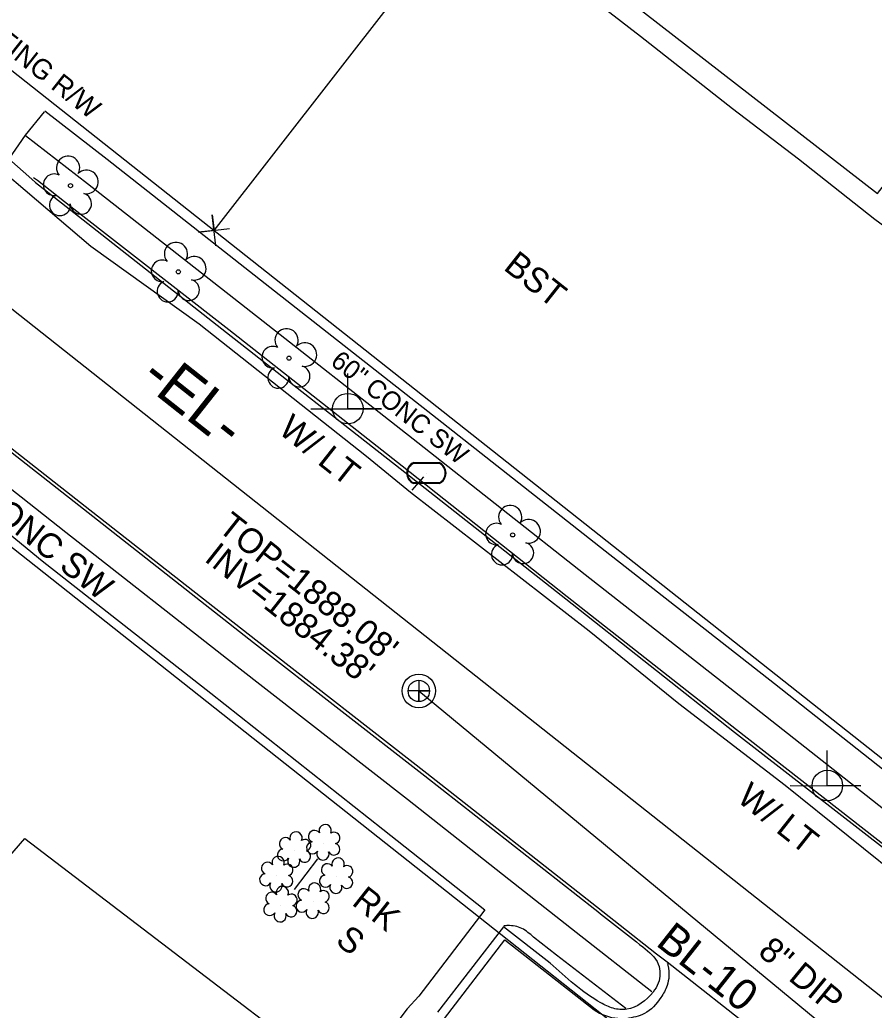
# Model space of a CAD drawing. Extents: x 553786 to 558838, y 502329 to 507342.
# Drawn here: x 558105.8 to 558242.8, y 506652.7 to 506811.5 of the extents above; entities that cross this region are included whole.
import ezdxf

# ---------------------------------------------------------------- set-up
doc = ezdxf.new("R2010")
doc.units = 0
for name, color, linetype in [('CTL Secondary Horizontal and Vertical Text', 7, 'Continuous'), ('Exist Other Culture Sign', 7, 'Continuous'), ('Exist Other Culture Sign Text', 7, 'Continuous'), ('Exist Right of Way Line Text', 7, 'Continuous'), ('Exist Roads EOP Other Text', 7, 'Continuous'), ('Exist Roads EOP Text', 7, 'Continuous'), ('Exist Utilities Power Joint Use Telephone CELL', 7, 'Continuous'), ('Exist Utilities Power Pole Text', 7, 'Continuous'), ('Exist Utilities Sanitary Sewer Manhole Text', 7, 'Continuous'), ('Exist Utilities Sanitary Sewer UG Line', 7, 'Continuous'), ('Exist Utilities Sanitary Sewer UG Line Invert Elevation', 7, 'Continuous'), ('Exist Utilities Sanitary Sewer UG Line Text', 7, 'Continuous'), ('Exist Vegetation Shrub CELL', 7, 'Continuous'), ('Exist Vegetation Tree CELL', 7, 'Continuous'), ('Prop CMT DNC', 7, 'Continuous'), ('Prop Drainage Structure Catch Basin Grate 840 03F Label', 7, 'Continuous'), ('Prop Drainage Structure Drop Inlet Grate 2 Wide Slots and Sag Grates 840 22 Label', 7, 'Continuous'), ('Prop Drainage Structure Drop Inlet Grate 840 16 Label', 7, 'Continuous'), ('Prop Drainage Structure Pipe Alternate 24in', 7, 'Continuous'), ('Prop Drainage Structure Pipe Alternate 36in', 7, 'Continuous'), ('Prop Drainage Structure Pipe RCP 15in Class III Label', 7, 'Continuous'), ('Prop Drainage Structure Plot Symbol 50 Scale', 7, 'Continuous'), ('Prop Drainage Structure Tops and Inverts LABEL', 7, 'Continuous'), ('Prop Erosion Rip Rap Pad Outlet for Jurisdictional Stream CELL', 7, 'Continuous'), ('Prop XS SE Text', 7, 'Continuous'), ('Sheet Layout Plan Border', 7, 'Continuous')]:
    doc.layers.add(name, color=color, linetype=linetype)

# ---------------------------------------------------------------- blocks, each defined once
blk = doc.blocks.new('EXIST UTILITIES SANITARY SEWER MANHOLE')
at = {"layer": 'Prop Drainage Structure Catch Basin Grate 840 03F Label'}
blk.add_lwpolyline([(0, 0.03425), (0, -0.03425), (0, 0), (0.03425, 0), (-0.03425, 0)], dxfattribs=at)
for radius in [0.05389, 0.03425]:
    blk.add_circle((0, 0), radius, dxfattribs=at)
blk = doc.blocks.new('EXIST UTILITIES WATER METER')
at = {"layer": 'Prop Drainage Structure Drop Inlet Grate 840 16 Label'}
blk.add_line((0, 0), (0, 0), dxfattribs=at)
for points in [[(-0.0408, 0.034), (0.0408, 0.034)], [(-0.0408, 0.0312), (0.0408, 0.0312)], [(0.0408, -0.0312), (-0.0413, -0.0312)], [(0.0408, -0.034), (-0.0413, -0.034)]]:
    blk.add_lwpolyline(points, dxfattribs=at)
for centre, radius, start, end in [((-0.0261, -0.0001), 0.0371, 113.178, 245.9794), ((0.0259, 0), 0.0371, 293.6483, 66.3084), ((-0.0259, -0.0001), 0.0347, 115.3009, 243.7824), ((0.0261, 0), 0.0345, 295.1272, 64.8728)]:
    blk.add_arc(centre, radius, start, end, dxfattribs=at)

msp = doc.modelspace()

# ---------------------------------------------------------------- linework, layer by layer
at = {"layer": 'Exist Other Culture Sign'}
msp.add_line((558149.85, 506672), (558153.56, 506676.92), dxfattribs=at)
at = {"layer": 'Exist Utilities Power Joint Use Telephone CELL'}
for p, q in [((558158.38, 506749.13), (558158.38, 506749.13)), ((558235.28, 506688.68), (558235.28, 506688.68))]:
    msp.add_line(p, q, dxfattribs=at)
for points in [[(558152.45, 506749.13), (558163.78, 506749.09), (558158.38, 506749.11), (558158.38, 506754.76)], [(558229.35, 506688.68), (558240.68, 506688.64), (558235.28, 506688.66), (558235.28, 506694.31)]]:
    msp.add_lwpolyline(points, dxfattribs=at)
for centre in [(558158.38, 506749.14), (558235.29, 506688.69)]:
    msp.add_circle(centre, 2.45, dxfattribs=at)
at = {"layer": 'Exist Utilities Sanitary Sewer UG Line'}
msp.add_line((558169.77, 506703.87), (558281.39, 506611.64), dxfattribs=at)
at = {"layer": 'Exist Vegetation Shrub CELL'}
for p, q in [((558154.52, 506679.41), (558154.52, 506679.41)), ((558149.84, 506678.25), (558149.84, 506678.25)), ((558146.98, 506674.3), (558146.98, 506674.3)), ((558156.59, 506674.06), (558156.59, 506674.06)), ((558147.65, 506669.49), (558147.65, 506669.49)), ((558152.82, 506670.04), (558152.82, 506670.04))]:
    msp.add_line(p, q, dxfattribs=at)
for centre, radius, start, end in [((558154.75, 506681.45), 0.99, 334.8391, 200.4717), ((558148.36, 506679.38), 0.968, 35.8908, 245.4216), ((558150.07, 506680.29), 0.99, 334.8391, 200.4717), ((558153.04, 506680.53), 0.968, 35.8908, 245.4216), ((558156.19, 506680.28), 0.929, 284.4567, 126.0861), ((558151.51, 506679.12), 0.929, 284.4567, 126.0861), ((558152.72, 506678.7), 0.955, 95.1099, 327.9534), ((558156.16, 506678.48), 0.937, 204.9913, 73.4601), ((558147.21, 506676.34), 0.99, 334.8391, 200.4717), ((558148.04, 506677.55), 0.955, 95.1099, 327.9534), ((558149.71, 506676.57), 0.984, 151.2797, 21.387), ((558151.48, 506677.32), 0.937, 204.9913, 73.4601), ((558154.39, 506677.72), 0.984, 151.2797, 21.387), ((558156.82, 506676.1), 0.99, 334.8391, 200.4717), ((558145.5, 506675.43), 0.968, 35.8908, 245.4216), ((558148.66, 506675.17), 0.929, 284.4567, 126.0861), ((558155.11, 506675.18), 0.968, 35.8908, 245.4216), ((558158.26, 506674.92), 0.929, 284.4567, 126.0861), ((558145.18, 506673.59), 0.955, 95.1099, 327.9534), ((558148.62, 506673.37), 0.937, 204.9913, 73.4601), ((558154.79, 506673.35), 0.955, 95.1099, 327.9534), ((558158.23, 506673.13), 0.937, 204.9913, 73.4601), ((558146.86, 506672.61), 0.984, 151.2797, 21.387), ((558147.88, 506671.53), 0.99, 334.8391, 200.4717), ((558153.05, 506672.08), 0.99, 334.8391, 200.4717), ((558156.46, 506672.37), 0.984, 151.2797, 21.387), ((558146.17, 506670.62), 0.968, 35.8908, 245.4216), ((558149.32, 506670.36), 0.929, 284.4567, 126.0861), ((558151.34, 506671.17), 0.968, 35.8908, 245.4216), ((558154.49, 506670.91), 0.929, 284.4567, 126.0861), ((558145.85, 506668.79), 0.955, 95.1099, 327.9534), ((558149.29, 506668.56), 0.937, 204.9913, 73.4601), ((558151.02, 506669.34), 0.955, 95.1099, 327.9534), ((558154.46, 506669.11), 0.937, 204.9913, 73.4601), ((558147.52, 506667.81), 0.984, 151.2797, 21.387), ((558152.69, 506668.36), 0.984, 151.2797, 21.387)]:
    msp.add_arc(centre, radius, start, end, dxfattribs=at)
at = {"layer": 'Exist Vegetation Tree CELL'}
for p, q in [((558113.9, 506784.9), (558113.9, 506784.9)), ((558131.19, 506771.08), (558131.19, 506771.08)), ((558148.94, 506757.23), (558148.94, 506757.23)), ((558184.82, 506728.88), (558184.82, 506728.88))]:
    msp.add_line(p, q, dxfattribs=at)
for centre in [(558113.9, 506784.9), (558131.19, 506771.08), (558148.94, 506757.23), (558184.82, 506728.88)]:
    msp.add_circle(centre, 0.326, dxfattribs=at)
for centre, radius, start, end in [((558113.51, 506787.77), 1.86, 330.1651, 219.7134), ((558111.29, 506785.05), 1.73, 62.6636, 279.3457), ((558116.44, 506785.49), 1.9, 257.1011, 134.1999), ((558115.57, 506782), 1.7, 181.2822, 74.56), ((558112.19, 506781.78), 1.69, 111.5671, 6.231), ((558130.81, 506773.95), 1.86, 330.1651, 219.7134), ((558128.59, 506771.23), 1.73, 62.6636, 279.3457), ((558133.74, 506771.66), 1.9, 257.1011, 134.1999), ((558129.49, 506767.95), 1.69, 111.5671, 6.231), ((558132.87, 506768.18), 1.7, 181.2822, 74.56), ((558148.55, 506760.11), 1.86, 330.1651, 219.7134), ((558151.49, 506757.82), 1.9, 257.1011, 134.1999), ((558146.33, 506757.39), 1.73, 62.6636, 279.3457), ((558147.24, 506754.11), 1.69, 111.5671, 6.231), ((558150.61, 506754.33), 1.7, 181.2822, 74.56), ((558184.43, 506731.75), 1.86, 330.1651, 219.7134), ((558187.37, 506729.47), 1.9, 257.1011, 134.1999), ((558182.21, 506729.03), 1.73, 62.6636, 279.3457), ((558183.11, 506725.76), 1.69, 111.5671, 6.231), ((558186.49, 506725.98), 1.7, 181.2822, 74.56)]:
    msp.add_arc(centre, radius, start, end, dxfattribs=at)
at = {"layer": 'Prop CMT DNC'}
msp.add_line((558136.92, 506777.73), (558136.92, 506777.73), dxfattribs=at)
msp.add_lwpolyline([(558137.22, 506775.25), (558136.61, 506780.21), (558136.92, 506777.73), (558134.43, 506777.42), (558139.4, 506778.03)], dxfattribs=at)
at = {"layer": 'Prop Drainage Structure Pipe Alternate 24in'}
msp.add_line((558168.71, 506736.05), (558170.58, 506738.2), dxfattribs=at)
msp.add_lwpolyline([(558061.02, 506824.48), (558076.77, 506810.62), (558092.78, 506795.92), (558117.16, 506775.2), (558134.53, 506762.73), (558161.4, 506741.5), (558168.42, 506735.76), (558197.07, 506713.51), (558211.45, 506701.86), (558228.52, 506688.74), (558248.75, 506672.51), (558265.05, 506659.63), (558283.87, 506644.89), (558296.8, 506634.76), (558312.61, 506622.53), (558332.21, 506607.01), (558356.73, 506587.18)], dxfattribs=at)
at = {"layer": 'Prop Drainage Structure Pipe Alternate 36in'}
for points in [[(557878.13, 506922), (557894.48, 506909.1), (557907.23, 506898.73), (557917, 506890.97), (557923.77, 506885.53), (557951.03, 506863.87), (557979.95, 506840.98), (558006.9, 506819.81), (558036.05, 506796.63), (558062.95, 506775.43), (558090.82, 506753.42), (558116.25, 506733.52), (558143.62, 506712.08), (558171.08, 506690.66), (558198.28, 506669.29), (558207.88, 506661.69), (558209.59, 506660.42), (558224.39, 506648.76), (558226.33, 506647.34), (558227.82, 506646.26), (558237.47, 506638.73)], [(558109.68, 506796.74), (558106.61, 506793.02), (558104.03, 506789.18), (558107.72, 506785.93), (558108.29, 506785.38), (558113.69, 506781.2), (558138.9, 506761.36), (558166.78, 506739.53), (558193.34, 506718.66), (558220.4, 506697.24), (558244.8, 506678.34), (558247.62, 506679.8), (558248.97, 506681.33), (558251.88, 506684.98)], [(558109.78, 506796.91), (558119.77, 506789.13), (558145.13, 506769.19), (558172.69, 506747.58), (558199.65, 506726.33), (558226.8, 506705.06), (558252.05, 506685.13)], [(558173.88, 506651.35), (558183.54, 506663.96), (558197.9, 506652.73)]]:
    msp.add_lwpolyline(points, dxfattribs=at)
msp.add_ellipse((558202.17, 506658.78), major_axis=(7.23, -1.71), ratio=0.998014, start_param=4.331342, end_param=4.880027, dxfattribs=at)
at = {"layer": 'Prop Drainage Structure Pipe RCP 15in Class III Label'}
for p, q in [((557858.16, 506921.65), (558370.6, 506516.46)), ((558076.12, 506825.79), (558265.11, 506676.36))]:
    msp.add_line(p, q, dxfattribs=at)
at = {"layer": 'Prop Drainage Structure Plot Symbol 50 Scale'}
for points in [[(557916.91, 506890.83), (557913.67, 506886.64), (557920.27, 506881.4), (557947.66, 506859.59), (557976.5, 506837.03), (558003.45, 506815.65), (558019.24, 506803.2), (558032.66, 506792.68), (558059.63, 506771.23), (558087.55, 506749.44), (558105.96, 506734.98), (558113.13, 506729.32), (558140.14, 506708.15), (558167.94, 506686.49), (558184.2, 506673.7), (558194.99, 506665.18), (558207.14, 506655.66)], [(558106.7, 506792.95), (558116.61, 506785.22), (558142.07, 506765.31), (558169.61, 506743.7), (558196.45, 506722.52), (558223.59, 506701.25), (558248.86, 506681.38)], [(558088.77, 506709.27), (558104.21, 506728.93), (558109.37, 506724.73), (558136.4, 506703.51), (558163.98, 506681.71), (558180.37, 506668.77), (558169.76, 506654.94)], [(558202.96, 506652.92), (558191.83, 506661.49), (558188.16, 506664.39)], [(558169.76, 506654.94), (558167.92, 506652.88), (558158.58, 506640.52)]]:
    msp.add_lwpolyline(points, dxfattribs=at)
for points in [[(558188.16, 506664.39), (558186.29, 506665.77), (558184.05, 506666.23), (558183.41, 506666.18)], [(558209.62, 506660.23), (558209.75, 506659.73), (558209.59, 506656.61), (558208.6, 506654.71), (558205.97, 506652.11), (558203.08, 506651.3), (558202.33, 506651.15)]]:
    msp.add_spline(points, degree=3, dxfattribs=at)
at = {"layer": 'Prop Drainage Structure Tops and Inverts LABEL'}
for points in [[(557917.43, 506890.02), (557923.46, 506885.09), (557950.76, 506863.39), (557979.57, 506840.67), (558006.57, 506819.34), (558035.73, 506796.23), (558062.67, 506775.06), (558090.32, 506753.15), (558115.96, 506733.08), (558143.27, 506711.66), (558170.75, 506690.26), (558197.99, 506668.87)], [(558316.89, 506788.12), (558311.82, 506781.65), (558289.37, 506752.7), (558287.96, 506751.64), (558286.61, 506751.23), (558285.36, 506751.25), (558284.14, 506751.63), (558283.09, 506752.3), (558273.71, 506759.39), (558254.15, 506774.52), (558251.43, 506774.68), (558249.34, 506775.2), (558247.94, 506775.77), (558242.92, 506779.49), (558230.67, 506789.15), (558220.09, 506797.2), (558205.35, 506808.8), (558182.14, 506826.79), (558154.62, 506848.29)], [(558107.98, 506786.19), (558108.62, 506785.76), (558113.93, 506781.57), (558139.27, 506761.82), (558167.1, 506739.94), (558193.58, 506719.02), (558220.72, 506697.67), (558245.11, 506678.67)], [(558190.81, 506660.23), (558183.35, 506666.04), (558172.75, 506652.34)]]:
    msp.add_lwpolyline(points, dxfattribs=at)
msp.add_spline([(558197.99, 506668.87), (558205.68, 506662.82), (558208.18, 506660.03), (558208.18, 506657.02), (558207.33, 506655.57), (558203.12, 506652.81), (558200.95, 506652.97), (558198.95, 506653.86), (558190.81, 506660.23)], degree=3, dxfattribs=at)
at = {"layer": 'Prop Erosion Rip Rap Pad Outlet for Jurisdictional Stream CELL'}
msp.add_lwpolyline([(558283.76, 506754.57), (558332.17, 506816.94), (558352.39, 506801.24), (558388.18, 506847.36), (558364.14, 506866.02), (558363.34, 506864.99), (558327.98, 506892.43), (558329.54, 506894.45), (558250.12, 506956.08), (558244.23, 506948.5), (558199.85, 506982.94), (558119.02, 506878.8), (558132.26, 506868.52), (558132.9, 506869.35), (558243.32, 506783.64), (558244.44, 506785.08)], close=True, dxfattribs=at)
msp.add_lwpolyline([(557986.62, 506761.46), (557998.12, 506775.67), (558035.79, 506746.69), (558024.21, 506732.72), (558066.55, 506699.28), (558073.69, 506708.4), (558086.66, 506698.35), (558079.2, 506689.68), (558100.36, 506673.1), (558106.6, 506680.21), (558179.53, 506624.52)], dxfattribs=at)
at = {"layer": 'Prop XS SE Text'}
msp.add_line((558136.92, 506777.73), (558265.72, 506943.09), dxfattribs=at)
at = {"layer": 'Sheet Layout Plan Border'}
msp.add_line((557876.77, 506945.18), (558407.17, 506525.79), dxfattribs=at)

# ---------------------------------------------------------------- block references
at = {"layer": 'Prop Drainage Structure Catch Basin Grate 840 03F Label', "xscale": 50, "yscale": 50}
msp.add_blockref('EXIST UTILITIES SANITARY SEWER MANHOLE', (558169.77, 506703.87), dxfattribs=at)
at = {"layer": 'Prop Drainage Structure Drop Inlet Grate 840 16 Label', "xscale": 50, "yscale": 50}
msp.add_blockref('EXIST UTILITIES WATER METER', (558170.98, 506738.81), dxfattribs=at)

# ---------------------------------------------------------------- texts
at = {"layer": 'CTL Secondary Horizontal and Vertical Text'}
msp.add_text('BL-10', height=5, rotation=321.6667, dxfattribs=at).set_placement((558207.6, 506663.19))
at = {"layer": 'Exist Other Culture Sign Text'}
for s, p in [('RK', (558158.85, 506669.69)), ('S', (558156.22, 506663.47))]:
    msp.add_text(s, height=4, rotation=321.6667, dxfattribs=at).set_placement(p)
at = {"layer": 'Exist Right of Way Line Text'}
msp.add_text('EXISTING R/W', height=3.2, rotation=321.6667, dxfattribs=at).set_placement((558093.97, 506813.72))
at = {"layer": 'Exist Roads EOP Other Text'}
for s, height, rotation, p in [('60" CONC SW', 3, 321.8583, (558155.43, 506756.31)), ('72" CONC SW', 4, 321.6436, (558091.07, 506740.04))]:
    msp.add_text(s, height=height, rotation=rotation, dxfattribs=at).set_placement(p)
at = {"layer": 'Exist Roads EOP Text'}
msp.add_text('BST', height=4, rotation=321.6667, dxfattribs=at).set_placement((558183.18, 506771.55))
at = {"layer": 'Exist Utilities Power Pole Text'}
for p in [(558147.05, 506745.36), (558220.58, 506686.32)]:
    msp.add_text('W/ LT', height=4, rotation=321.6667, dxfattribs=at).set_placement(p)
at = {"layer": 'Exist Utilities Sanitary Sewer Manhole Text'}
msp.add_text("TOP=1888.08'", height=4, rotation=321.6667, dxfattribs=at).set_placement((558137.35, 506729.69))
at = {"layer": 'Exist Utilities Sanitary Sewer UG Line Invert Elevation'}
msp.add_text("INV=1884.38'", height=4, rotation=321.6667, dxfattribs=at).set_placement((558135.2, 506724.81))
at = {"layer": 'Exist Utilities Sanitary Sewer UG Line Text'}
msp.add_text('8" DIP', height=4, rotation=320.4313, dxfattribs=at).set_placement((558223.98, 506661.67))
at = {"layer": 'Prop Drainage Structure Drop Inlet Grate 2 Wide Slots and Sag Grates 840 22 Label'}
msp.add_text('-EL-', height=7, rotation=321.6667, dxfattribs=at).set_placement((558124.79, 506753.5))

doc.saveas('drawing.dxf')
